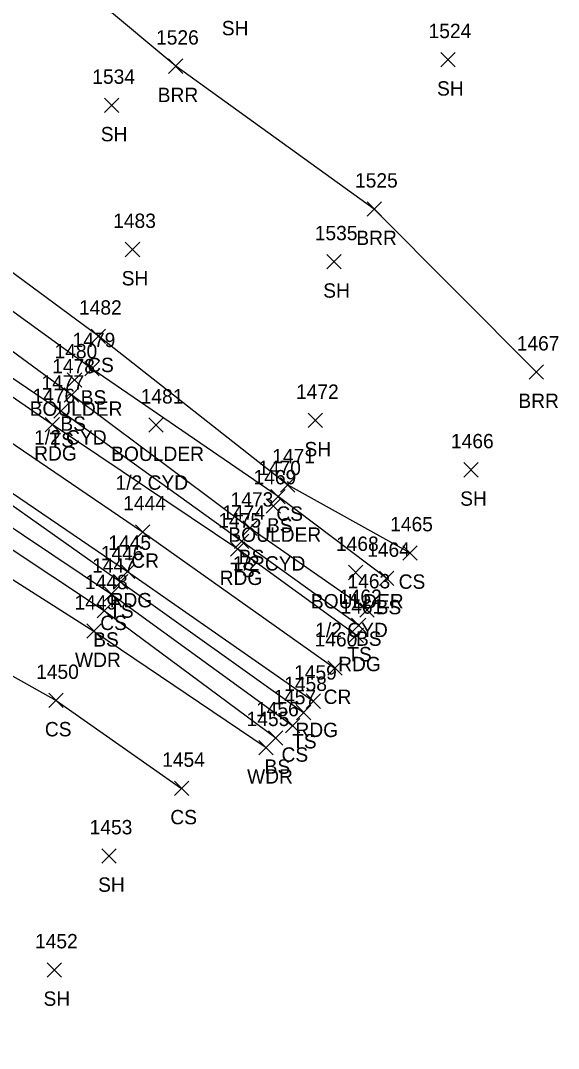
# Model space of a CAD drawing. Extents: x 1469310 to 1475157, y 493997 to 498873.
# Drawn here: x 1469740.5 to 1469815.5, y 498333.7 to 498476.8 of the extents above; entities that cross this region are included whole.
import ezdxf

# ---------------------------------------------------------------- set-up
doc = ezdxf.new("R2010")
doc.units = 0
for name, color, linetype in [('L_A', 7, 'Continuous'), ('L_C', 7, 'Continuous'), ('L_I', 7, 'Continuous'), ('L_TIC', 7, 'Continuous'), ('LABL', 7, 'Continuous'), ('LAWA', 7, 'Continuous'), ('LELB', 7, 'Continuous'), ('P_A', 7, 'Continuous'), ('P_I', 7, 'Continuous'), ('P_TIC', 7, 'Continuous'), ('PEU', 7, 'Continuous'), ('PRC', 7, 'Continuous')]:
    doc.layers.add(name, color=color, linetype=linetype)

msp = doc.modelspace()

# ---------------------------------------------------------------- linework, layer by layer
at = {"layer": 'L_TIC'}
for points in [[(1469799.07, 498470.31), (1469801.07, 498472.31)], [(1469801.07, 498470.31), (1469799.07, 498472.31)], [(1469761.16, 498469.41), (1469763.16, 498471.41)], [(1469763.16, 498469.41), (1469761.16, 498471.41)], [(1469752.22, 498463.95), (1469754.22, 498465.95)], [(1469754.22, 498463.95), (1469752.22, 498465.95)], [(1469788.82, 498449.51), (1469790.82, 498451.51)], [(1469790.82, 498449.51), (1469788.82, 498451.51)], [(1469755.13, 498443.89), (1469757.13, 498445.89)], [(1469757.13, 498443.89), (1469755.13, 498445.89)], [(1469783.22, 498442.18), (1469785.22, 498444.18)], [(1469785.22, 498442.18), (1469783.22, 498444.18)], [(1469750.37, 498431.82), (1469752.37, 498433.82)], [(1469752.37, 498431.82), (1469750.37, 498433.82)], [(1469749.48, 498427.3), (1469751.48, 498429.3)], [(1469751.48, 498427.3), (1469749.48, 498429.3)], [(1469811.4, 498426.83), (1469813.4, 498428.83)], [(1469813.4, 498426.83), (1469811.4, 498428.83)], [(1469747.05, 498425.74), (1469749.05, 498427.74)], [(1469749.05, 498425.74), (1469747.05, 498427.74)], [(1469746.63, 498423.65), (1469748.63, 498425.65)], [(1469748.63, 498423.65), (1469746.63, 498425.65)], [(1469745.15, 498421.39), (1469747.15, 498423.39)], [(1469747.15, 498421.39), (1469745.15, 498423.39)], [(1469758.4, 498419.45), (1469760.4, 498421.45)], [(1469760.4, 498419.45), (1469758.4, 498421.45)], [(1469780.61, 498420.1), (1469782.61, 498422.1)], [(1469782.61, 498420.1), (1469780.61, 498422.1)], [(1469802.3, 498413.22), (1469804.3, 498415.22)], [(1469804.3, 498413.22), (1469802.3, 498415.22)], [(1469776.73, 498411.13), (1469778.73, 498413.13)], [(1469778.73, 498411.13), (1469776.73, 498413.13)], [(1469775.42, 498409.49), (1469777.42, 498411.49)], [(1469777.42, 498409.49), (1469775.42, 498411.49)], [(1469774.74, 498408.2), (1469776.74, 498410.2)], [(1469776.74, 498408.2), (1469774.74, 498410.2)], [(1469771.49, 498405.1), (1469773.49, 498407.1)], [(1469773.49, 498405.1), (1469771.49, 498407.1)], [(1469770.33, 498403.28), (1469772.33, 498405.28)], [(1469772.33, 498403.28), (1469770.33, 498405.28)], [(1469793.77, 498401.66), (1469795.77, 498403.66)], [(1469795.77, 498401.66), (1469793.77, 498403.66)], [(1469786.22, 498398.93), (1469788.22, 498400.93)], [(1469788.22, 498398.93), (1469786.22, 498400.93)], [(1469753.46, 498397.63), (1469755.46, 498399.63)], [(1469755.46, 498397.63), (1469753.46, 498399.63)], [(1469790.56, 498398.11), (1469792.56, 498400.11)], [(1469792.56, 498398.11), (1469790.56, 498400.11)], [(1469752.19, 498395.92), (1469754.19, 498397.92)], [(1469754.19, 498395.92), (1469752.19, 498397.92)], [(1469751.21, 498393.61), (1469753.21, 498395.61)], [(1469753.21, 498393.61), (1469751.21, 498395.61)], [(1469787.82, 498393.72), (1469789.82, 498395.72)], [(1469789.82, 498393.72), (1469787.82, 498395.72)], [(1469786.64, 498391.56), (1469788.64, 498393.56)], [(1469788.64, 498391.56), (1469786.64, 498393.56)], [(1469749.75, 498390.77), (1469751.75, 498392.77)], [(1469751.75, 498390.77), (1469749.75, 498392.77)], [(1469744.48, 498381.12), (1469746.48, 498383.12)], [(1469746.48, 498381.12), (1469744.48, 498383.12)], [(1469778.96, 498379.44), (1469780.96, 498381.44)], [(1469780.96, 498379.44), (1469778.96, 498381.44)], [(1469777.45, 498377.59), (1469779.45, 498379.59)], [(1469779.45, 498377.59), (1469777.45, 498379.59)], [(1469775.09, 498375.91), (1469777.09, 498377.91)], [(1469777.09, 498375.91), (1469775.09, 498377.91)], [(1469773.73, 498374.55), (1469775.73, 498376.55)], [(1469775.73, 498374.55), (1469773.73, 498376.55)], [(1469761.96, 498368.88), (1469763.96, 498370.88)], [(1469763.96, 498368.88), (1469761.96, 498370.88)], [(1469751.86, 498359.48), (1469753.86, 498361.48)], [(1469753.86, 498359.48), (1469751.86, 498361.48)], [(1469744.24, 498343.61), (1469746.24, 498345.61)], [(1469746.24, 498343.61), (1469744.24, 498345.61)]]:
    msp.add_lwpolyline(points, dxfattribs=at)
at = {"layer": 'LABL'}
msp.add_lwpolyline([(1469812.4, 498427.83), (1469789.82, 498450.51), (1469762.16, 498470.41), (1469730.76, 498496.59), (1469695.43, 498518.47), (1469668.13, 498535.82), (1469658.49, 498545.19), (1469647.1, 498565.82), (1469633.19, 498572.64), (1469634.36, 498584.72)], dxfattribs=at)
at = {"layer": 'LAWA'}
msp.add_lwpolyline([(1469662.11, 498434.67), (1469668.7, 498443.7), (1469693.89, 498425.89), (1469720.54, 498410.93), (1469750.75, 498391.77), (1469774.73, 498375.55)], dxfattribs=at)
at = {"layer": 'LELB'}
for points in [[(1469788.82, 498394.72), (1469772.49, 498406.1), (1469747.63, 498424.65), (1469713.94, 498449.33), (1469681.33, 498467.82), (1469654.97, 498486.97), (1469638.09, 498508.74), (1469624.13, 498529.31), (1469618.93, 498538.23), (1469619.74, 498548.83)], [(1469787.64, 498392.56), (1469771.33, 498404.28), (1469746.15, 498422.39), (1469712.15, 498445.44), (1469680.51, 498465.06), (1469652.75, 498484.35), (1469633.1, 498503.6), (1469618.23, 498526.44), (1469608.67, 498544.39), (1469612.83, 498546.46)], [(1469794.77, 498402.66), (1469777.73, 498412.13), (1469751.37, 498432.82), (1469719.33, 498456.43), (1469684.35, 498475.42), (1469659.61, 498491.8), (1469644.94, 498514.45), (1469661.82, 498527.77), (1469668.13, 498535.82)], [(1469791.56, 498399.11), (1469776.42, 498410.49), (1469750.48, 498428.3), (1469716.94, 498452.54), (1469682.84, 498471.48), (1469659.61, 498491.8)], [(1469648.57, 498334.34), (1469648.24, 498371.84), (1469647.81, 498403.48), (1469643.5, 498432.91), (1469646.9, 498444.52), (1469665.9, 498452.6), (1469701.4, 498434.28), (1469725.86, 498418.8), (1469754.46, 498398.63), (1469779.96, 498380.44)], [(1469648.57, 498334.34), (1469651.55, 498371.14), (1469654.15, 498404.21), (1469648.51, 498432.09), (1469652.26, 498442.54), (1469671.04, 498448.92), (1469700.19, 498431.88), (1469724.42, 498416.16), (1469753.19, 498396.92), (1469778.45, 498378.59)], [(1469653.02, 498333.68), (1469656.67, 498371.22), (1469661.64, 498405.68), (1469657.65, 498434.35), (1469658.27, 498442.14), (1469668.7, 498443.7), (1469697.25, 498429.19), (1469723.26, 498413.8), (1469752.21, 498394.61), (1469776.09, 498376.91)], [(1469662.11, 498434.67), (1469687.06, 498416.67), (1469709.56, 498402.23), (1469745.48, 498382.12), (1469762.96, 498369.88)]]:
    msp.add_lwpolyline(points, dxfattribs=at)
at = {"layer": 'P_TIC'}
for points in [[(1469743.94, 498419.51), (1469745.94, 498421.51)], [(1469745.94, 498419.51), (1469743.94, 498421.51)], [(1469756.53, 498404.58), (1469758.53, 498406.58)], [(1469758.53, 498404.58), (1469756.53, 498406.58)], [(1469769.79, 498402.19), (1469771.79, 498404.19)], [(1469771.79, 498402.19), (1469769.79, 498404.19)], [(1469754.45, 498399.08), (1469756.45, 498401.08)], [(1469756.45, 498399.08), (1469754.45, 498401.08)], [(1469786.29, 498390.19), (1469788.29, 498392.19)], [(1469788.29, 498390.19), (1469786.29, 498392.19)], [(1469783.33, 498385.63), (1469785.33, 498387.63)], [(1469785.33, 498385.63), (1469783.33, 498387.63)], [(1469780.34, 498381.02), (1469782.34, 498383.02)], [(1469782.34, 498381.02), (1469780.34, 498383.02)]]:
    msp.add_lwpolyline(points, dxfattribs=at)
at = {"layer": 'PEU'}
for points in [[(1469787.29, 498391.19), (1469770.79, 498403.19), (1469744.94, 498420.51), (1469711.23, 498443.77), (1469680.07, 498463.21), (1469651.58, 498483.41), (1469630.63, 498501.52), (1469612.52, 498523.24), (1469599.41, 498542.19), (1469591.57, 498556.6), (1469575.61, 498583.06), (1469557.31, 498607.49), (1469540.09, 498628.65), (1469536.24, 498634.99), (1469514.98, 498658.51), (1469490.83, 498684.27), (1469472.69, 498702.57), (1469444.89, 498732.16), (1469424.97, 498753.74), (1469411.28, 498767.74), (1469386.83, 498794.07), (1469360.47, 498820.44)], [(1469644.47, 498334.17), (1469644.25, 498371.57), (1469641.38, 498402.11), (1469637.73, 498433.09), (1469640.39, 498440.51), (1469646.92, 498449.33), (1469658.69, 498455.86), (1469670.4, 498454.48), (1469672.75, 498453.58), (1469702.13, 498435.56), (1469726.39, 498419.79), (1469755.45, 498400.08), (1469781.34, 498382.02)]]:
    msp.add_lwpolyline(points, dxfattribs=at)
at = {"layer": 'PRC'}
msp.add_lwpolyline([(1469611.93, 498509.33), (1469635.59, 498485.96), (1469656.26, 498471.44), (1469676.23, 498459.15), (1469677.31, 498457.92), (1469704.76, 498441.38), (1469729.86, 498424.4), (1469757.53, 498405.58), (1469784.33, 498386.63)], dxfattribs=at)

# ---------------------------------------------------------------- texts
at = {"layer": 'L_A'}
for s, p in [('SH', (1469768.57, 498474.71)), ('SH', (1469798.56, 498466.31)), ('BRR', (1469759.64, 498465.41)), ('SH', (1469751.71, 498459.95)), ('BRR', (1469787.31, 498445.51)), ('SH', (1469754.62, 498439.89)), ('SH', (1469782.7, 498438.18)), ('CS', (1469749.81, 498427.82)), ('BS', (1469748.92, 498423.3)), ('BOULDER', (1469741.8, 498421.74)), ('BRR', (1469809.89, 498422.83)), ('BS', (1469746.07, 498419.65)), ('TS', (1469744.56, 498417.39)), ('SH', (1469780.09, 498416.1)), ('BOULDER', (1469753.16, 498415.45)), ('SH', (1469801.78, 498409.22)), ('CS', (1469776.17, 498407.13)), ('BS', (1469774.86, 498405.49)), ('BOULDER', (1469769.49, 498404.2)), ('BS', (1469770.93, 498401.1)), ('TS', (1469769.74, 498399.28)), ('CS', (1469793.21, 498397.66)), ('BOULDER', (1469780.98, 498394.93)), ('TS', (1469752.87, 498393.63)), ('BS', (1469790, 498394.11)), ('CS', (1469751.63, 498391.92)), ('BS', (1469750.65, 498389.61)), ('BS', (1469787.26, 498389.72)), ('TS', (1469786.05, 498387.56)), ('WDR', (1469748.12, 498386.77)), ('CS', (1469743.92, 498377.12)), ('TS', (1469778.37, 498375.44)), ('CS', (1469776.89, 498373.59)), ('BS', (1469774.53, 498371.91)), ('WDR', (1469772.09, 498370.55)), ('CS', (1469761.4, 498364.88)), ('SH', (1469751.34, 498355.48)), ('SH', (1469743.73, 498339.61))]:
    msp.add_text(s, height=2, dxfattribs=at).set_placement(p)
at = {"layer": 'L_C'}
for p in [(1469742.42, 498417.74), (1469753.77, 498411.45), (1469770.11, 498400.2), (1469781.59, 498390.93)]:
    msp.add_text('1/2 CYD', height=2, dxfattribs=at).set_placement(p)
at = {"layer": 'L_I'}
for s, p in [('1526', (1469759.41, 498473.41)), ('1524', (1469797.38, 498474.31)), ('1534', (1469750.53, 498467.95)), ('1525', (1469787.13, 498453.51)), ('1483', (1469753.44, 498447.89)), ('1535', (1469781.52, 498446.18)), ('1482', (1469748.68, 498435.82)), ('1479', (1469747.78, 498431.3)), ('1467', (1469809.66, 498430.83)), ('1480', (1469745.27, 498429.74)), ('1478', (1469744.94, 498427.65)), ('1477', (1469743.45, 498425.39)), ('1481', (1469757.27, 498423.45)), ('1472', (1469778.91, 498424.1)), ('1466', (1469800.5, 498417.22)), ('1471', (1469775.6, 498415.13)), ('1470', (1469773.64, 498413.49)), ('1469', (1469772.99, 498412.2)), ('1473', (1469769.8, 498409.1)), ('1474', (1469768.63, 498407.28)), ('1465', (1469792.03, 498405.66)), ('1446', (1469751.71, 498401.63)), ('1468', (1469784.48, 498402.93)), ('1464', (1469788.82, 498402.11)), ('1447', (1469750.5, 498399.92)), ('1448', (1469749.51, 498397.61)), ('1463', (1469786.08, 498397.72)), ('1449', (1469748.05, 498394.77)), ('1462', (1469784.9, 498395.56)), ('1450', (1469742.7, 498385.12)), ('1458', (1469777.27, 498383.44)), ('1457', (1469775.76, 498381.59)), ('1456', (1469773.34, 498379.91)), ('1455', (1469772.03, 498378.55)), ('1454', (1469760.26, 498372.88)), ('1453', (1469750.16, 498363.48)), ('1452', (1469742.55, 498347.61))]:
    msp.add_text(s, height=2, dxfattribs=at).set_placement(p)
at = {"layer": 'P_A'}
for s, p in [('RDG', (1469742.43, 498415.51)), ('CR', (1469755.96, 498400.58)), ('RDG', (1469768.27, 498398.19)), ('RDG', (1469752.94, 498395.08)), ('RDG', (1469784.78, 498386.19)), ('CR', (1469782.76, 498381.63)), ('RDG', (1469778.83, 498377.02))]:
    msp.add_text(s, height=2, dxfattribs=at).set_placement(p)
at = {"layer": 'P_I'}
for s, p in [('1476', (1469742.19, 498423.51)), ('1444', (1469754.83, 498408.58)), ('1475', (1469768.09, 498406.19)), ('1445', (1469752.76, 498403.08)), ('1461', (1469785.11, 498394.19)), ('1460', (1469781.5, 498389.63)), ('1459', (1469778.64, 498385.02))]:
    msp.add_text(s, height=2, dxfattribs=at).set_placement(p)

doc.saveas('drawing.dxf')
